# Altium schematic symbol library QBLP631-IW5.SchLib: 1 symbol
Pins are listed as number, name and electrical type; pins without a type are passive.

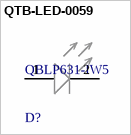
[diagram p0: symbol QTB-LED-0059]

## QTB-LED-0059
designator D?, comment QBLP631-IW5
LED WHITE DIFFUSED 0805 SMD; Manufacturer: QT Brightek (QTB); Lens Size: 1.25mm; Luminous Intensity: 85mcd; Test Current: 5mA; Lens Color: Yellow; Lens Style: Flat; Forward Voltage: 2.9V
footprint QBLP631-IW
pins: 1 ANODE (+), 2 CATHODE (-)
